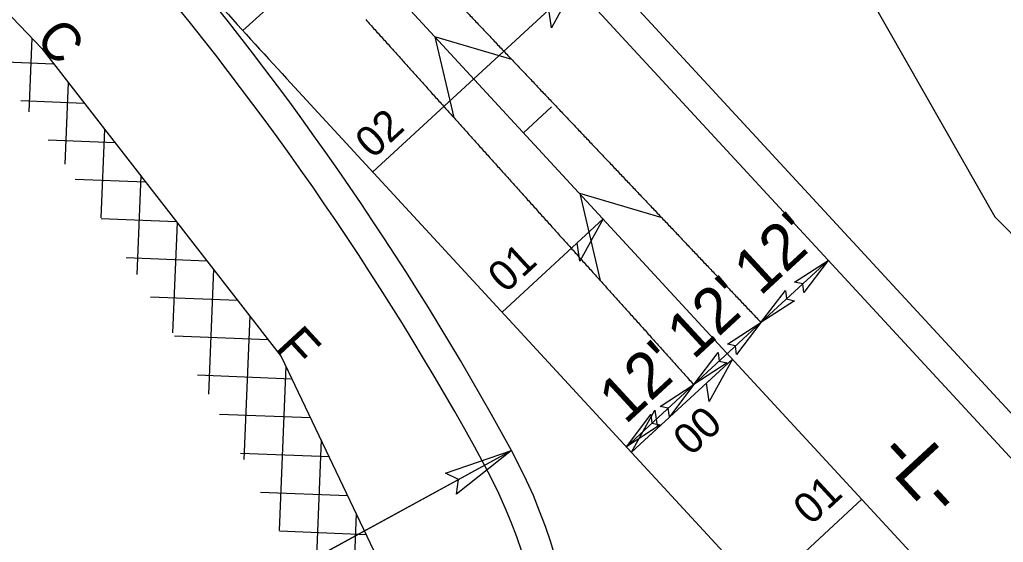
# Model space of a CAD drawing. Extents: x 1702862 to 1704514, y 793768 to 796215.
# Drawn here: x 1703198.5 to 1703327.4, y 795246.9 to 795315.4 of the extents above; entities that cross this region are included whole.
import ezdxf

# ---------------------------------------------------------------- set-up
doc = ezdxf.new("R2010")
doc.units = 0
for name, color, linetype in [('Prop Dimension', 7, 'Continuous'), ('Prop Dimension Text', 7, 'Continuous'), ('Prop EOT', 7, 'Continuous'), ('Prop Horizontal Alignment', 7, 'Continuous'), ('Prop Horizontal Alignment Direction Label', 7, 'Continuous'), ('Prop Horizontal Alignment Tick Small', 7, 'Continuous'), ('Prop Lane Lines', 7, 'Continuous'), ('Prop Paint Stripe', 7, 'Continuous'), ('Prop Paved Shoulder', 7, 'Continuous'), ('Prop Rem of Exist Asph Pvmt', 7, 'Continuous'), ('Prop SS Cut Line', 7, 'Continuous'), ('Prop SS Fill Line', 7, 'Continuous'), ('Prop SS Misc', 7, 'Continuous'), ('Prop SS Transition Line', 7, 'Continuous'), ('Prop Superelevation  Arrow CELL', 7, 'Continuous'), ('Prop Superelevation Label', 7, 'Continuous'), ('Prop Terminator CELL', 7, 'Continuous')]:
    doc.layers.add(name, color=color, linetype=linetype)

msp = doc.modelspace()

# ---------------------------------------------------------------- linework, layer by layer
at = {"layer": 'Prop Dimension'}
for p, q in [((1703295.63, 795275.75), (1703304.45, 795283.89)), ((1703286.82, 795267.61), (1703295.63, 795275.75)), ((1703278, 795259.47), (1703286.82, 795267.61)), ((1702911.8, 795067.36), (1703262.92, 795258.97)), ((1703201.47, 795225.44), (1703262.92, 795258.97))]:
    msp.add_line(p, q, dxfattribs=at)
at = {"layer": 'Prop EOT'}
msp.add_line((1703259.9, 795332.15), (1703737.14, 794815.13), dxfattribs=at)
for centre, radius, start, end in [((1702911.8, 795067.36), 400, 28.6224, 41.0304), ((1703201.47, 795225.44), 70, 332.0106, 28.6224)]:
    msp.add_arc(centre, radius, start, end, dxfattribs=at)
at = {"layer": 'Prop Horizontal Alignment'}
msp.add_line((1703246.67, 795319.94), (1703723.92, 794802.92), dxfattribs=at)
at = {"layer": 'Prop Horizontal Alignment Tick Small'}
msp.add_line((1703264.51, 795300.62), (1703268.19, 795304.01), dxfattribs=at)
at = {"layer": 'Prop Lane Lines'}
msp.add_line((1703233.45, 795307.73), (1703326.99, 795206.39), dxfattribs=at)
msp.add_arc((1703981.48, 795998.22), 1018, 221.141, 222.70907, dxfattribs=at)
for points in [[(1703251.4, 795322.4), (1703252, 795321.77), (1703252.6, 795321.14), (1703253.19, 795320.51), (1703253.79, 795319.88), (1703254.39, 795319.25), (1703254.99, 795318.62), (1703255.59, 795317.99), (1703256.18, 795317.36), (1703256.78, 795316.73), (1703257.38, 795316.1), (1703257.98, 795315.47), (1703258.57, 795314.84), (1703259.17, 795314.21), (1703259.77, 795313.58), (1703260.37, 795312.95), (1703260.96, 795312.31), (1703261.56, 795311.68), (1703262.16, 795311.05), (1703262.76, 795310.42), (1703263.36, 795309.79), (1703263.95, 795309.16), (1703264.55, 795308.53), (1703265.15, 795307.9), (1703265.75, 795307.27), (1703266.34, 795306.64), (1703266.94, 795306.01), (1703267.54, 795305.38), (1703268.14, 795304.75), (1703268.74, 795304.12), (1703269.33, 795303.49), (1703269.93, 795302.86), (1703270.53, 795302.23), (1703271.13, 795301.6), (1703271.72, 795300.97), (1703272.32, 795300.34), (1703272.92, 795299.71), (1703273.52, 795299.07), (1703274.12, 795298.44), (1703274.71, 795297.81), (1703275.31, 795297.18), (1703275.91, 795296.55), (1703276.51, 795295.92), (1703277.1, 795295.29), (1703277.7, 795294.66), (1703278.3, 795294.03), (1703278.9, 795293.4), (1703279.49, 795292.77), (1703280.09, 795292.14), (1703280.69, 795291.51), (1703281.29, 795290.88), (1703281.89, 795290.25), (1703282.48, 795289.62), (1703283.08, 795288.99), (1703283.68, 795288.36), (1703284.28, 795287.73), (1703284.87, 795287.1), (1703285.47, 795286.46), (1703286.07, 795285.83), (1703286.67, 795285.2), (1703287.27, 795284.57), (1703287.86, 795283.94), (1703288.46, 795283.31), (1703289.06, 795282.68), (1703289.66, 795282.05), (1703290.25, 795281.42), (1703290.85, 795280.79), (1703291.45, 795280.16), (1703292.05, 795279.53), (1703292.65, 795278.9), (1703293.24, 795278.27), (1703293.84, 795277.64), (1703294.44, 795277.01), (1703295.63, 795275.75)], [(1703243.84, 795315.43), (1703244.42, 795314.78), (1703245, 795314.13), (1703245.59, 795313.49), (1703246.17, 795312.84), (1703246.75, 795312.2), (1703247.33, 795311.55), (1703247.91, 795310.9), (1703248.49, 795310.26), (1703249.07, 795309.61), (1703249.65, 795308.96), (1703250.23, 795308.32), (1703250.81, 795307.67), (1703251.39, 795307.03), (1703251.97, 795306.38), (1703252.55, 795305.73), (1703253.13, 795305.09), (1703253.72, 795304.44), (1703254.3, 795303.79), (1703254.88, 795303.15), (1703255.46, 795302.5), (1703256.04, 795301.86), (1703256.62, 795301.21), (1703257.2, 795300.56), (1703257.78, 795299.92), (1703258.36, 795299.27), (1703258.94, 795298.62), (1703259.52, 795297.98), (1703260.1, 795297.33), (1703260.68, 795296.69), (1703261.26, 795296.04), (1703261.85, 795295.39), (1703262.43, 795294.75), (1703263.01, 795294.1), (1703263.59, 795293.46), (1703264.17, 795292.81), (1703264.75, 795292.16), (1703265.33, 795291.52), (1703265.91, 795290.87), (1703266.49, 795290.22), (1703267.07, 795289.58), (1703267.65, 795288.93), (1703268.23, 795288.29), (1703268.81, 795287.64), (1703269.39, 795286.99), (1703269.98, 795286.35), (1703270.56, 795285.7), (1703271.14, 795285.05), (1703271.72, 795284.41), (1703272.3, 795283.76), (1703272.88, 795283.12), (1703273.46, 795282.47), (1703274.04, 795281.82), (1703274.62, 795281.18), (1703275.2, 795280.53), (1703275.78, 795279.88), (1703276.36, 795279.24), (1703276.94, 795278.59), (1703277.52, 795277.95), (1703278.11, 795277.3), (1703278.69, 795276.65), (1703279.27, 795276.01), (1703279.85, 795275.36), (1703280.43, 795274.72), (1703281.01, 795274.07), (1703281.59, 795273.42), (1703282.17, 795272.78), (1703282.75, 795272.13), (1703283.33, 795271.48), (1703283.91, 795270.84), (1703284.49, 795270.19), (1703285.07, 795269.55), (1703285.65, 795268.9), (1703286.82, 795267.61)]]:
    msp.add_spline(points, degree=3, dxfattribs=at)
at = {"layer": 'Prop Paint Stripe'}
for p, q in [((1703262.96, 795310.21), (1703252.9, 795313.2)), ((1703252.9, 795313.2), (1703255.38, 795302.59)), ((1703282.66, 795289.44), (1703271.88, 795292.64)), ((1703271.88, 795292.64), (1703274.54, 795281.27)), ((1703295.63, 795275.75), (1703286.82, 795267.61))]:
    msp.add_line(p, q, dxfattribs=at)
for points in [[(1703251.4, 795322.4), (1703252, 795321.77), (1703252.6, 795321.14), (1703253.19, 795320.51), (1703253.79, 795319.88), (1703254.39, 795319.25), (1703254.99, 795318.62), (1703255.59, 795317.99), (1703256.18, 795317.36), (1703256.78, 795316.73), (1703257.38, 795316.1), (1703257.98, 795315.47), (1703258.57, 795314.84), (1703259.17, 795314.21), (1703259.77, 795313.58), (1703260.37, 795312.95), (1703260.96, 795312.31), (1703261.56, 795311.68), (1703262.16, 795311.05), (1703262.76, 795310.42), (1703263.36, 795309.79), (1703263.95, 795309.16), (1703264.55, 795308.53), (1703265.15, 795307.9), (1703265.75, 795307.27), (1703266.34, 795306.64), (1703266.94, 795306.01), (1703267.54, 795305.38), (1703268.14, 795304.75), (1703268.74, 795304.12), (1703269.33, 795303.49), (1703269.93, 795302.86), (1703270.53, 795302.23), (1703271.13, 795301.6), (1703271.72, 795300.97), (1703272.32, 795300.34), (1703272.92, 795299.71), (1703273.52, 795299.07), (1703274.12, 795298.44), (1703274.71, 795297.81), (1703275.31, 795297.18), (1703275.91, 795296.55), (1703276.51, 795295.92), (1703277.1, 795295.29), (1703277.7, 795294.66), (1703278.3, 795294.03), (1703278.9, 795293.4), (1703279.49, 795292.77), (1703280.09, 795292.14), (1703280.69, 795291.51), (1703281.29, 795290.88), (1703281.89, 795290.25), (1703282.48, 795289.62), (1703283.08, 795288.99), (1703283.68, 795288.36), (1703284.28, 795287.73), (1703284.87, 795287.1), (1703285.47, 795286.46), (1703286.07, 795285.83), (1703286.67, 795285.2), (1703287.27, 795284.57), (1703287.86, 795283.94), (1703288.46, 795283.31), (1703289.06, 795282.68), (1703289.66, 795282.05), (1703290.25, 795281.42), (1703290.85, 795280.79), (1703291.45, 795280.16), (1703292.05, 795279.53), (1703292.65, 795278.9), (1703293.24, 795278.27), (1703293.84, 795277.64), (1703294.44, 795277.01), (1703295.63, 795275.75)], [(1703243.84, 795315.43), (1703244.42, 795314.78), (1703245, 795314.13), (1703245.59, 795313.49), (1703246.17, 795312.84), (1703246.75, 795312.2), (1703247.33, 795311.55), (1703247.91, 795310.9), (1703248.49, 795310.26), (1703249.07, 795309.61), (1703249.65, 795308.96), (1703250.23, 795308.32), (1703250.81, 795307.67), (1703251.39, 795307.03), (1703251.97, 795306.38), (1703252.55, 795305.73), (1703253.13, 795305.09), (1703253.72, 795304.44), (1703254.3, 795303.79), (1703254.88, 795303.15), (1703255.46, 795302.5), (1703256.04, 795301.86), (1703256.62, 795301.21), (1703257.2, 795300.56), (1703257.78, 795299.92), (1703258.36, 795299.27), (1703258.94, 795298.62), (1703259.52, 795297.98), (1703260.1, 795297.33), (1703260.68, 795296.69), (1703261.26, 795296.04), (1703261.85, 795295.39), (1703262.43, 795294.75), (1703263.01, 795294.1), (1703263.59, 795293.46), (1703264.17, 795292.81), (1703264.75, 795292.16), (1703265.33, 795291.52), (1703265.91, 795290.87), (1703266.49, 795290.22), (1703267.07, 795289.58), (1703267.65, 795288.93), (1703268.23, 795288.29), (1703268.81, 795287.64), (1703269.39, 795286.99), (1703269.98, 795286.35), (1703270.56, 795285.7), (1703271.14, 795285.05), (1703271.72, 795284.41), (1703272.3, 795283.76), (1703272.88, 795283.12), (1703273.46, 795282.47), (1703274.04, 795281.82), (1703274.62, 795281.18), (1703275.2, 795280.53), (1703275.78, 795279.88), (1703276.36, 795279.24), (1703276.94, 795278.59), (1703277.52, 795277.95), (1703278.11, 795277.3), (1703278.69, 795276.65), (1703279.27, 795276.01), (1703279.85, 795275.36), (1703280.43, 795274.72), (1703281.01, 795274.07), (1703281.59, 795273.42), (1703282.17, 795272.78), (1703282.75, 795272.13), (1703283.33, 795271.48), (1703283.91, 795270.84), (1703284.49, 795270.19), (1703285.07, 795269.55), (1703285.65, 795268.9), (1703286.82, 795267.61)]]:
    msp.add_spline(points, degree=3, dxfattribs=at)
at = {"layer": 'Prop Paved Shoulder'}
msp.add_line((1703262.84, 795334.86), (1703386.66, 795200.72), dxfattribs=at)
for centre, radius, start, end in [((1702911.8, 795067.36), 396, 28.6224, 41.0304), ((1703201.47, 795225.44), 66, 332.0106, 28.6224)]:
    msp.add_arc(centre, radius, start, end, dxfattribs=at)
at = {"layer": 'Prop Rem of Exist Asph Pvmt'}
for p, q in [((1703200.04, 795313.02), (1703199.66, 795303.34)), ((1703195.07, 795309.97), (1703202.91, 795309.66)), ((1703204.82, 795307.21), (1703204.39, 795296.49)), ((1703198.63, 795304.83), (1703206.93, 795304.49)), ((1703209.58, 795301.09), (1703209.11, 795289.44)), ((1703202.19, 795299.68), (1703210.95, 795299.33)), ((1703205.72, 795294.53), (1703214.96, 795294.16)), ((1703214.33, 795294.97), (1703213.82, 795282.04)), ((1703209.14, 795289.39), (1703218.98, 795289)), ((1703219.09, 795288.86), (1703218.51, 795274.38)), ((1703212.42, 795284.26), (1703223, 795283.84)), ((1703223.85, 795282.74), (1703223.2, 795266.35)), ((1703215.63, 795279.13), (1703227.01, 795278.67)), ((1703228.61, 795276.62), (1703227.86, 795257.79)), ((1703218.74, 795274), (1703231.03, 795273.51)), ((1703233.35, 795270.03), (1703232.49, 795248.49)), ((1703221.75, 795268.87), (1703234.14, 795268.38)), ((1703224.65, 795263.75), (1703236.58, 795263.28)), ((1703237.97, 795260.36), (1703236.95, 795234.91)), ((1703227.41, 795258.64), (1703239.01, 795258.17)), ((1703230.04, 795253.53), (1703241.45, 795253.07)), ((1703242.59, 795250.69), (1703240.46, 795197.58)), ((1703232.52, 795248.43), (1703243.88, 795247.97))]:
    msp.add_line(p, q, dxfattribs=at)
at = {"layer": 'Prop SS Cut Line'}
msp.add_line((1703165.24, 795349.27), (1703201.37, 795311.64), dxfattribs=at)
at = {"layer": 'Prop SS Fill Line'}
for p, q in [((1703326.3, 795289.61), (1703361.26, 795253.83)), ((1703232.75, 795271.3), (1703247.45, 795240.51))]:
    msp.add_line(p, q, dxfattribs=at)
at = {"layer": 'Prop SS Transition Line'}
for p, q in [((1703300.88, 795334.19), (1703326.3, 795289.61)), ((1703201.37, 795311.64), (1703232.75, 795271.3))]:
    msp.add_line(p, q, dxfattribs=at)
at = {"layer": 'Prop Superelevation  Arrow CELL'}
for p, q in [((1703241.05, 795326.09), (1703227.72, 795313.99)), ((1703257.98, 795307.69), (1703271.21, 795319.9)), ((1703257.98, 795307.69), (1703244.75, 795295.48)), ((1703274.94, 795289.32), (1703261.71, 795277.11)), ((1703291.89, 795270.95), (1703278.67, 795258.74)), ((1703308.85, 795252.58), (1703295.63, 795240.37))]:
    msp.add_line(p, q, dxfattribs=at)
for points in [[(1703271.21, 795319.9), (1703268.16, 795314.36), (1703267.81, 795316.76)], [(1703274.94, 795289.32), (1703271.89, 795283.78), (1703271.54, 795286.18)], [(1703291.89, 795270.95), (1703288.84, 795265.41), (1703288.5, 795267.81)], [(1703278.67, 795258.74), (1703281.72, 795264.28), (1703282.07, 795261.88)]]:
    msp.add_lwpolyline(points, close=True, dxfattribs=at)
at = {"layer": 'Prop Terminator CELL'}
for points in [[(1703300.04, 795281.03), (1703304.45, 795283.89), (1703301.25, 795279.68), (1703301.11, 795280.8)], [(1703300.04, 795278.6), (1703295.63, 795275.75), (1703298.83, 795279.95), (1703298.97, 795278.83)], [(1703291.23, 795272.89), (1703295.63, 795275.75), (1703292.43, 795271.54), (1703292.3, 795272.67)], [(1703291.22, 795270.46), (1703286.82, 795267.61), (1703290.02, 795271.81), (1703290.15, 795270.69)], [(1703282.41, 795264.75), (1703286.82, 795267.61), (1703283.62, 795263.4), (1703283.48, 795264.53)], [(1703282.41, 795262.32), (1703278, 795259.47), (1703281.2, 795263.67), (1703281.34, 795262.55)], [(1703254.27, 795256.02), (1703262.92, 795258.97), (1703255.74, 795253.23), (1703255.98, 795255.19)]]:
    msp.add_lwpolyline(points, close=True, dxfattribs=at)

# ---------------------------------------------------------------- texts
at = {"layer": 'Prop Dimension Text'}
for p in [(1703295.53, 795279.1), (1703286.76, 795270.75), (1703277.85, 795262.27)]:
    msp.add_text("12'", height=6, rotation=42.7091, dxfattribs=at).set_placement(p)
at = {"layer": 'Prop Horizontal Alignment Direction Label'}
msp.add_text('-L-', height=7, rotation=312.7091, dxfattribs=at).set_placement((1703310.6, 795258.2))
at = {"layer": 'Prop SS Misc'}
for s, rotation, p in [('C', 311.3511, (1703200.36, 795312.79)), ('F', 312.7091, (1703231.79, 795272.34))]:
    msp.add_text(s, height=5, rotation=rotation, dxfattribs=at).set_placement(p)
at = {"layer": 'Prop Superelevation Label'}
for s, p in [('02', (1703244.75, 795297.08)), ('01', (1703262.14, 795279.48)), ('00', (1703286.43, 795258.12)), ('01', (1703302.17, 795249.06))]:
    msp.add_text(s, height=4, rotation=42.7091, dxfattribs=at).set_placement(p)

doc.saveas('drawing.dxf')
